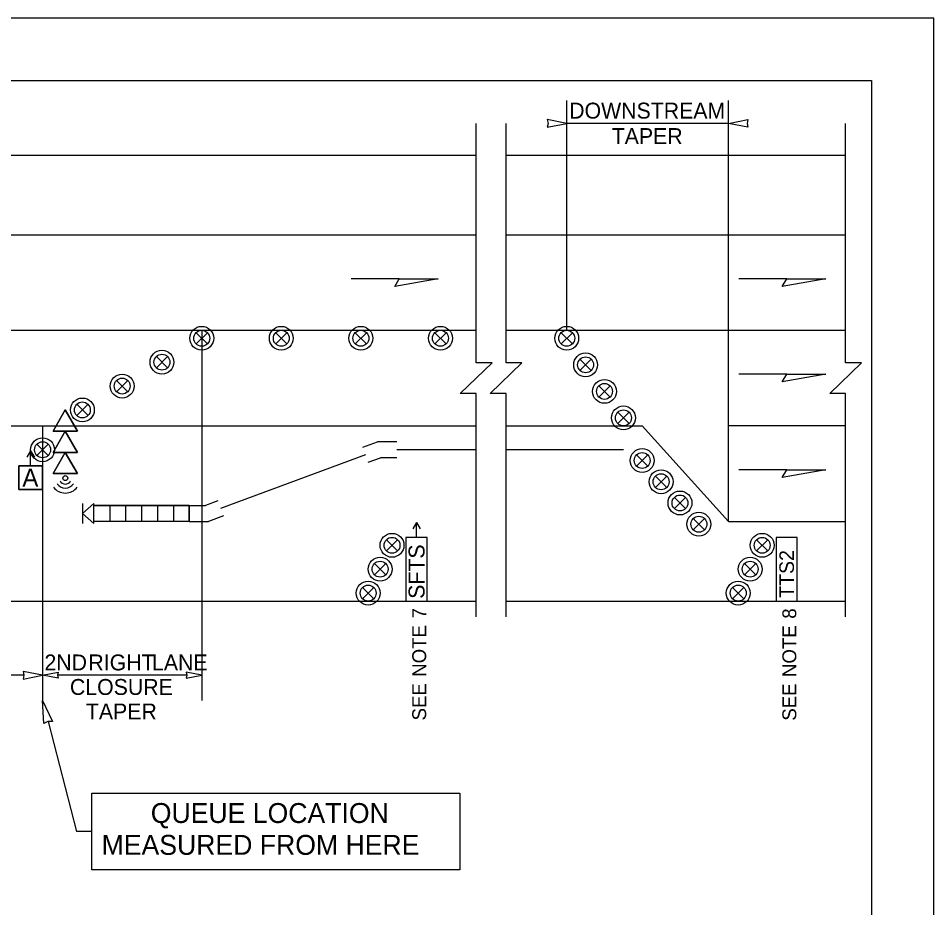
# Model space of a CAD drawing. Extents: x 99999.1 to 100055.7, y 99995 to 100017.5.
# Drawn here: x 100031.461 to 100036.062, y 100006.219 to 100010.687 of the extents above; entities that cross this region are included whole.
import ezdxf

# ---------------------------------------------------------------- set-up
doc = ezdxf.new("R2010")
doc.units = 0
for name, color, linetype in [('DS_GE_GenericRandomBlue', 7, 'Continuous'), ('RD_ED_ShoulderPavedEdge', 7, 'Continuous'), ('RD_MK_LineEdgeWhite', 7, 'Continuous'), ('RD_MK_LineEdgeYellow', 7, 'Continuous'), ('RD_MK_LineLane', 7, 'Continuous'), ('SH_GI_PlotLimits', 7, 'Continuous'), ('SH_GI_SheetBorder', 7, 'Continuous'), ('TR_WZ_BarrierTemp', 7, 'Continuous'), ('TR_WZ_PortableSignMountBlk-Wht', 7, 'Continuous'), ('TR_WZ_SequentialArrowSign', 7, 'Continuous'), ('TR_WZ_TrafficSafetyDrum', 7, 'Continuous'), ('TR_WZ_TrafficSafetyDrum2', 7, 'Continuous'), ('TR_WZ_WorkZoneDetails', 7, 'Continuous'), ('TR_WZ_WorkZoneTextCurrent', 7, 'Continuous')]:
    doc.layers.add(name, color=color, linetype=linetype)

msp = doc.modelspace()

# ---------------------------------------------------------------- linework, layer by layer
at = {"layer": 'DS_GE_GenericRandomBlue'}
for p, q in [((100032.3205, 100008.2397), (100031.8405, 100008.2397)), ((100031.8405, 100008.2397), (100032.3205, 100008.2397)), ((100031.8405, 100008.1597), (100031.8405, 100008.2397)), ((100031.9205, 100008.2397), (100031.9205, 100008.1597)), ((100032.0005, 100008.2397), (100032.0005, 100008.1597)), ((100032.0805, 100008.2397), (100032.0805, 100008.1597)), ((100032.1605, 100008.2397), (100032.1605, 100008.1597)), ((100032.2405, 100008.2397), (100032.2405, 100008.1597)), ((100032.3205, 100008.1597), (100032.3205, 100008.2397)), ((100032.3205, 100008.2397), (100032.3205, 100008.1597)), ((100032.3205, 100008.1597), (100031.8405, 100008.1597)), ((100032.3205, 100008.1597), (100031.8405, 100008.1597))]:
    msp.add_line(p, q, dxfattribs=at)
at = {"layer": 'RD_ED_ShoulderPavedEdge'}
for p, q in [((100020.1028, 100009.9997), (100033.7628, 100009.9997)), ((100033.9128, 100009.9997), (100035.62, 100009.9997)), ((100020.1028, 100007.7597), (100033.7628, 100007.7597)), ((100033.9128, 100007.7597), (100035.62, 100007.7597)), ((100033.9128, 100007.7597), (100035.62, 100007.7597))]:
    msp.add_line(p, q, dxfattribs=at)
at = {"layer": 'RD_MK_LineEdgeWhite'}
for p, q in [((100030.7831, 100008.6397), (100033.7628, 100008.6397)), ((100033.9128, 100008.6397), (100034.5972, 100008.6397)), ((100034.5972, 100008.6397), (100035.0304, 100008.1597)), ((100035.0304, 100008.1597), (100035.62, 100008.1597))]:
    msp.add_line(p, q, dxfattribs=at)
at = {"layer": 'RD_MK_LineEdgeYellow'}
for p, q in [((100020.1028, 100009.5997), (100033.7628, 100009.5997)), ((100033.9128, 100009.5997), (100035.62, 100009.5997))]:
    msp.add_line(p, q, dxfattribs=at)
at = {"layer": 'RD_MK_LineLane'}
for points in [[(100033.7628, 100009.1197), (100020.1028, 100009.1197)], [(100035.62, 100009.1197), (100033.9128, 100009.1197)], [(100035.62, 100008.6397), (100035.0304, 100008.6397)]]:
    msp.add_lwpolyline(points, dxfattribs=at)
at = {"layer": 'SH_GI_PlotLimits'}
msp.add_lwpolyline([(100019.0625, 99999.6875), (100036.0625, 99999.6875), (100036.0625, 100010.6875), (100019.0625, 100010.6875)], close=True, dxfattribs=at)
at = {"layer": 'SH_GI_SheetBorder'}
for p, q in [((100020, 100010.375), (100035.75, 100010.375)), ((100035.75, 100010.375), (100035.75, 100000))]:
    msp.add_line(p, q, dxfattribs=at)
at = {"layer": 'TR_WZ_BarrierTemp'}
for p, q in [((100033.2061, 100008.4946), (100032.478, 100008.2249)), ((100033.7628, 100008.5197), (100033.3635, 100008.5197)), ((100034.5029, 100008.5197), (100033.9128, 100008.5197))]:
    msp.add_line(p, q, dxfattribs=at)
at = {"layer": 'TR_WZ_PortableSignMountBlk-Wht'}
msp.add_line((100031.7831, 100008.2497), (100031.7831, 100008.1497), dxfattribs=at)
msp.add_lwpolyline([(100031.7831, 100008.1998), (100031.8405, 100008.1497), (100031.8405, 100008.2497)], close=True, dxfattribs=at)
at = {"layer": 'TR_WZ_SequentialArrowSign'}
for points in [[(100031.6974, 100008.7197), (100031.6356, 100008.6131), (100031.6974, 100008.6131), (100031.7591, 100008.6131), (100031.6974, 100008.7197)], [(100031.7591, 100008.6131), (100031.6974, 100008.6131), (100031.6356, 100008.6131), (100031.6974, 100008.7197), (100031.7591, 100008.6131)], [(100031.6974, 100008.6131), (100031.6356, 100008.5064), (100031.6974, 100008.5064), (100031.7591, 100008.5064), (100031.6974, 100008.6131)], [(100031.7591, 100008.5064), (100031.6974, 100008.5064), (100031.6356, 100008.5064), (100031.6974, 100008.6131), (100031.7591, 100008.5064)], [(100031.6974, 100008.5064), (100031.6356, 100008.3997), (100031.7591, 100008.3997), (100031.6974, 100008.5064)], [(100031.7591, 100008.3997), (100031.6356, 100008.3997), (100031.6974, 100008.5064), (100031.7591, 100008.3997)]]:
    msp.add_lwpolyline(points, dxfattribs=at)
msp.add_circle((100031.6974, 100008.3772), 0.0125, dxfattribs=at)
for radius, start, end in [(0.03, 207.158, 332.842), (0.075, 217.3291, 322.6709), (0.05, 213.9782, 326.0218)]:
    msp.add_arc((100031.6974, 100008.3772), radius, start, end, dxfattribs=at)
at = {"layer": 'TR_WZ_TrafficSafetyDrum'}
for p, q in [((100032.3549, 100009.108), (100032.4114, 100009.0515)), ((100032.4114, 100009.108), (100032.3549, 100009.0515)), ((100032.7549, 100009.108), (100032.8114, 100009.0515)), ((100032.8114, 100009.108), (100032.7549, 100009.0515)), ((100033.1549, 100009.108), (100033.2114, 100009.0515)), ((100033.2114, 100009.108), (100033.1549, 100009.0515)), ((100033.5549, 100009.108), (100033.6114, 100009.0515)), ((100033.6114, 100009.108), (100033.5549, 100009.0515)), ((100034.1895, 100009.108), (100034.2461, 100009.0515)), ((100034.2461, 100009.108), (100034.1895, 100009.0515)), ((100032.1549, 100008.988), (100032.2114, 100008.9315)), ((100032.2114, 100008.988), (100032.1549, 100008.9315)), ((100034.2845, 100008.9747), (100034.3411, 100008.9181)), ((100034.3411, 100008.9747), (100034.2845, 100008.9181)), ((100031.9549, 100008.868), (100032.0114, 100008.8115)), ((100032.0114, 100008.868), (100031.9549, 100008.8115)), ((100034.3796, 100008.8414), (100034.4361, 100008.7848)), ((100034.4361, 100008.8414), (100034.3796, 100008.7848)), ((100031.7549, 100008.748), (100031.8114, 100008.6915)), ((100031.8114, 100008.748), (100031.7549, 100008.6915)), ((100034.4746, 100008.708), (100034.5311, 100008.6515)), ((100034.5311, 100008.708), (100034.4746, 100008.6515)), ((100031.5549, 100008.548), (100031.6114, 100008.4915)), ((100031.6114, 100008.548), (100031.5549, 100008.4915)), ((100034.5689, 100008.4941), (100034.6255, 100008.4375)), ((100034.6255, 100008.4941), (100034.5689, 100008.4375)), ((100034.6639, 100008.3874), (100034.7205, 100008.3308)), ((100034.7205, 100008.3874), (100034.6639, 100008.3308)), ((100034.7589, 100008.2807), (100034.8155, 100008.2241)), ((100034.8155, 100008.2807), (100034.7589, 100008.2241)), ((100034.854, 100008.174), (100034.9105, 100008.1175)), ((100034.9105, 100008.174), (100034.854, 100008.1175))]:
    msp.add_line(p, q, dxfattribs=at)
for centre, radius in [((100032.3831, 100009.0798), 0.06), ((100032.3831, 100009.0798), 0.06), ((100032.7831, 100009.0798), 0.06), ((100032.7831, 100009.0798), 0.06), ((100033.1831, 100009.0798), 0.06), ((100033.1831, 100009.0798), 0.06), ((100033.5831, 100009.0798), 0.06), ((100033.5831, 100009.0798), 0.06), ((100034.2178, 100009.0798), 0.06), ((100034.2178, 100009.0798), 0.06), ((100032.3831, 100009.0798), 0.04), ((100032.7831, 100009.0798), 0.04), ((100033.1831, 100009.0798), 0.04), ((100033.5831, 100009.0798), 0.04), ((100034.2178, 100009.0798), 0.04), ((100032.1831, 100008.9598), 0.06), ((100032.1831, 100008.9598), 0.06), ((100034.3128, 100008.9464), 0.06), ((100034.3128, 100008.9464), 0.06), ((100032.1831, 100008.9598), 0.04), ((100034.3128, 100008.9464), 0.04), ((100031.9831, 100008.8398), 0.06), ((100031.9831, 100008.8398), 0.06), ((100031.9831, 100008.8398), 0.04), ((100034.4078, 100008.8131), 0.06), ((100034.4078, 100008.8131), 0.06), ((100034.4078, 100008.8131), 0.04), ((100031.7831, 100008.7198), 0.06), ((100031.7831, 100008.7198), 0.06), ((100031.7831, 100008.7198), 0.04), ((100034.5029, 100008.6797), 0.06), ((100034.5029, 100008.6797), 0.06), ((100034.5029, 100008.6797), 0.04), ((100031.5831, 100008.5198), 0.06), ((100031.5831, 100008.5198), 0.06), ((100031.5831, 100008.5198), 0.04), ((100034.5972, 100008.4658), 0.06), ((100034.5972, 100008.4658), 0.06), ((100034.5972, 100008.4658), 0.04), ((100034.6922, 100008.3591), 0.06), ((100034.6922, 100008.3591), 0.06), ((100034.6922, 100008.3591), 0.04), ((100034.7872, 100008.2524), 0.06), ((100034.7872, 100008.2524), 0.06), ((100034.7872, 100008.2524), 0.04), ((100034.8822, 100008.1457), 0.06), ((100034.8822, 100008.1457), 0.06), ((100034.8822, 100008.1457), 0.04)]:
    msp.add_circle(centre, radius, dxfattribs=at)
at = {"layer": 'TR_WZ_TrafficSafetyDrum2'}
for p, q in [((100033.3113, 100008.068), (100033.3679, 100008.0115)), ((100033.3679, 100008.068), (100033.3113, 100008.0115)), ((100035.1719, 100008.068), (100035.2284, 100008.0115)), ((100035.2284, 100008.068), (100035.1719, 100008.0115)), ((100033.2513, 100007.948), (100033.3079, 100007.8915)), ((100033.3079, 100007.948), (100033.2513, 100007.8915)), ((100035.1119, 100007.948), (100035.1684, 100007.8915)), ((100035.1684, 100007.948), (100035.1119, 100007.8915)), ((100033.1913, 100007.828), (100033.2479, 100007.7715)), ((100033.2479, 100007.828), (100033.1913, 100007.7715)), ((100035.0519, 100007.828), (100035.1084, 100007.7715)), ((100035.1084, 100007.828), (100035.0519, 100007.7715))]:
    msp.add_line(p, q, dxfattribs=at)
for centre, radius in [((100033.3396, 100008.0397), 0.06), ((100033.3396, 100008.0397), 0.06), ((100033.3396, 100008.0397), 0.04), ((100035.2001, 100008.0397), 0.06), ((100035.2001, 100008.0397), 0.06), ((100035.2001, 100008.0397), 0.04), ((100033.2796, 100007.9197), 0.06), ((100033.2796, 100007.9197), 0.06), ((100033.2796, 100007.9197), 0.04), ((100035.1401, 100007.9197), 0.06), ((100035.1401, 100007.9197), 0.06), ((100035.1401, 100007.9197), 0.04), ((100033.2196, 100007.7997), 0.06), ((100033.2196, 100007.7997), 0.06), ((100035.0801, 100007.7997), 0.06), ((100035.0801, 100007.7997), 0.06), ((100033.2196, 100007.7997), 0.04), ((100035.0801, 100007.7997), 0.04)]:
    msp.add_circle(centre, radius, dxfattribs=at)
at = {"layer": 'TR_WZ_WorkZoneDetails'}
for p, q in [((100034.2178, 100009.1197), (100034.2178, 100010.275)), ((100035.0304, 100008.1597), (100035.0304, 100010.275)), ((100035.0304, 100010.1597), (100034.2178, 100010.1597)), ((100033.3752, 100009.379), (100033.1341, 100009.379)), ((100035.3235, 100009.379), (100035.0824, 100009.379)), ((100032.3831, 100009.1197), (100032.3831, 100007.2597)), ((100035.3235, 100008.899), (100035.0824, 100008.899)), ((100031.5831, 100008.6397), (100031.5831, 100007.2597)), ((100033.3635, 100008.5597), (100033.2668, 100008.5597)), ((100031.5231, 100008.5147), (100031.5044, 100008.4823)), ((100031.5231, 100008.4397), (100031.5231, 100008.5147)), ((100031.5231, 100008.5147), (100031.5419, 100008.4823)), ((100033.3635, 100008.4797), (100033.2812, 100008.4797)), ((100035.3235, 100008.419), (100035.0824, 100008.419)), ((100032.3205, 100008.2397), (100032.4028, 100008.2397)), ((100032.3205, 100008.1597), (100032.4172, 100008.1597)), ((100033.463, 100008.1547), (100033.4442, 100008.1223)), ((100033.463, 100008.1547), (100033.4817, 100008.1223)), ((100033.463, 100008.0797), (100033.463, 100008.1547)), ((100031.4894, 100007.3871), (100030.8769, 100007.3871)), ((100032.3081, 100007.3871), (100031.6581, 100007.3871))]:
    msp.add_line(p, q, dxfattribs=at)
for points in [[(100033.7628, 100007.6797), (100033.7628, 100008.8023), (100033.6828, 100008.8023), (100033.8428, 100008.9572), (100033.7628, 100008.9572), (100033.7628, 100010.1597)], [(100033.9128, 100007.6797), (100033.9128, 100008.8023), (100033.8328, 100008.8023), (100033.9928, 100008.9572), (100033.9128, 100008.9572), (100033.9128, 100010.1597)], [(100035.62, 100007.6797), (100035.62, 100008.8023), (100035.54, 100008.8023), (100035.7, 100008.9572), (100035.62, 100008.9572), (100035.62, 100010.1597)], [(100033.1922, 100008.5321), (100033.2668, 100008.5597)], [(100033.22, 100008.4571), (100033.2812, 100008.4797)], [(100031.4631, 100008.4397), (100031.4631, 100008.3197), (100031.5831, 100008.3197), (100031.5831, 100008.4397), (100031.5231, 100008.4397), (100031.4631, 100008.4397)], [(100032.4641, 100008.2624), (100032.4028, 100008.2397)], [(100032.4919, 100008.1874), (100032.4172, 100008.1597)], [(100033.5163, 100007.7597), (100033.5163, 100008.0797), (100033.4096, 100008.0797), (100033.4096, 100007.7597), (100033.5163, 100007.7597)], [(100035.3768, 100007.7597), (100035.3768, 100008.0797), (100035.2701, 100008.0797), (100035.2701, 100007.7597), (100035.3768, 100007.7597)]]:
    msp.add_lwpolyline(points, dxfattribs=at)
for points in [[(100034.2178, 100010.1597), (100034.1195, 100010.179), (100034.1241, 100010.1597), (100034.1195, 100010.1405)], [(100035.0304, 100010.1597), (100035.1286, 100010.179), (100035.1241, 100010.1597), (100035.1286, 100010.1405)], [(100033.5718, 100009.379), (100033.353, 100009.3405), (100033.3752, 100009.379)], [(100035.52, 100009.379), (100035.3012, 100009.3405), (100035.3235, 100009.379)], [(100035.52, 100008.899), (100035.3012, 100008.8605), (100035.3235, 100008.899)], [(100031.4631, 100008.4397), (100031.5831, 100008.4397), (100031.5831, 100008.3197), (100031.4631, 100008.3197)], [(100035.52, 100008.419), (100035.3012, 100008.3805), (100035.3235, 100008.419)], [(100033.5163, 100007.7597), (100033.5163, 100008.0797), (100033.4096, 100008.0797), (100033.4096, 100007.7597)], [(100035.3768, 100007.7597), (100035.3768, 100008.0797), (100035.2701, 100008.0797), (100035.2701, 100007.7597)], [(100031.5831, 100007.3871), (100031.4849, 100007.4064), (100031.4894, 100007.3871), (100031.4849, 100007.3678)], [(100031.5831, 100007.3871), (100031.6618, 100007.4025), (100031.6581, 100007.3871), (100031.6618, 100007.3717)], [(100032.3831, 100007.3871), (100032.3045, 100007.4025), (100032.3081, 100007.3871), (100032.3045, 100007.3717)]]:
    msp.add_lwpolyline(points, close=True, dxfattribs=at)
at = {"layer": 'TR_WZ_WorkZoneTextCurrent'}
for p in [(100031.6104, 100007.1547), (100031.83, 100006.602)]:
    msp.add_line(p, (100031.7538, 100006.602), dxfattribs=at)
for points in [[(100031.5831, 100007.2597), (100031.6333, 100007.1551), (100031.6103, 100007.1546), (100031.5901, 100007.1439)], [(100031.83, 100006.7945), (100033.6805, 100006.7945), (100033.6805, 100006.4095), (100031.83, 100006.4095)]]:
    msp.add_lwpolyline(points, close=True, dxfattribs=at)

# ---------------------------------------------------------------- texts
at = {"layer": 'TR_WZ_WorkZoneDetails'}
msp.add_text('A', height=0.09, dxfattribs=at).set_placement((100031.4815, 100008.3347))
for s, height, p in [('SFTS', 0.08, (100033.503, 100007.7707)), ('TTS2', 0.07333, (100035.3601, 100007.7759)), ('7', 0.07, (100033.5113, 100007.6722)), ('8', 0.07, (100035.3718, 100007.6709)), ('NOTE', 0.07, (100033.5113, 100007.3791)), ('NOTE', 0.07, (100035.3718, 100007.3777)), ('SEE', 0.07, (100033.5113, 100007.1598)), ('SEE', 0.07, (100035.3718, 100007.1585))]:
    msp.add_text(s, height=height, rotation=90, dxfattribs=at).set_placement(p)
at = {"layer": 'TR_WZ_WorkZoneTextCurrent'}
for s, height, p in [('DOWNSTREAM', 0.08, (100034.2302, 100010.1837)), ('TAPER', 0.08, (100034.4439, 100010.0557)), ('2ND', 0.08, (100031.5924, 100007.4111)), ('RIGHT', 0.08, (100031.8134, 100007.4111)), ('LANE', 0.08, (100032.1331, 100007.4111)), ('CLOSURE', 0.08, (100031.7205, 100007.2879)), ('TAPER', 0.08, (100031.8007, 100007.1647)), ('QUEUE LOCATION', 0.1, (100032.127, 100006.6445)), ('MEASURED FROM HERE', 0.1, (100031.88, 100006.4845))]:
    msp.add_text(s, height=height, dxfattribs=at).set_placement(p)

doc.saveas('drawing.dxf')
